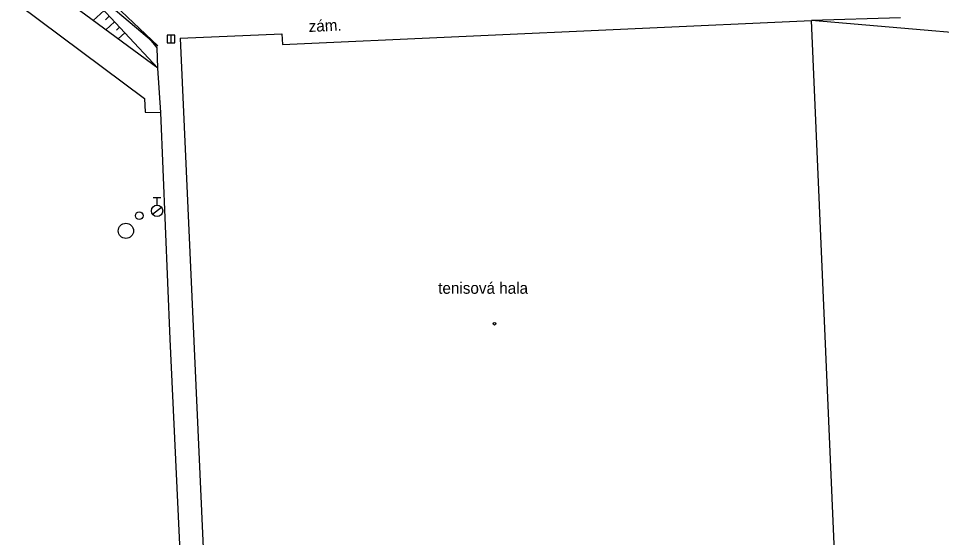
# Model space of a CAD drawing. Extents: x -737812 to -729375, y -1123000 to -1115500.
# Drawn here: x -736312.1 to -736251.3, y -1118316.3 to -1118282.1 of the extents above; entities that cross this region are included whole.
import ezdxf

# ---------------------------------------------------------------- set-up
doc = ezdxf.new("R2010")
doc.units = 0
for name, color, linetype in [('Doplněk polohopisu', 7, 'Continuous'), ('Pomocné popisy', 7, 'Continuous'), ('Popisy budov', 7, 'Continuous'), ('Povr_ zn_ inž_ sítí - kan_', 7, 'Continuous'), ('Povr_ zn_ inž_ sítí - vod_', 7, 'Continuous'), ('Stavební objekty', 7, 'Continuous'), ('Výškopis', 7, 'Continuous'), ('Značky druhů budov', 7, 'Continuous')]:
    doc.layers.add(name, color=color, linetype=linetype)

msp = doc.modelspace()

# ---------------------------------------------------------------- linework, layer by layer
at = {"layer": 'Doplněk polohopisu'}
for p, q in [((-736302.92, -1118285.4), (-736310.03, -1118280.13)), ((-736254.05, -1118282.07), (-736259.89, -1118282.26)), ((-736302.95, -1118284.06), (-736303.41, -1118283.49)), ((-736302.92, -1118285.4), (-736302.95, -1118284.06)), ((-736302.71, -1118288.3), (-736302.92, -1118285.4)), ((-736302.09, -1118303.23), (-736302.71, -1118288.3)), ((-736300.95, -1118328.07), (-736302.09, -1118303.23))]:
    msp.add_line(p, q, dxfattribs=at)
msp.add_lwpolyline([(-736312.08, -1118281.2), (-736303.78, -1118287.39), (-736303.74, -1118288.28), (-736302.71, -1118288.3)], dxfattribs=at)
at = {"layer": 'Povr_ zn_ inž_ sítí - kan_'}
msp.add_line((-736302.05, -1118283.22), (-736302.05, -1118283.72), dxfattribs=at)
msp.add_lwpolyline([(-736302.301, -1118283.22), (-736302.301, -1118283.721), (-736301.799, -1118283.72), (-736301.8, -1118283.22)], close=True, dxfattribs=at)
msp.add_circle((-736305.01, -1118296.1), 0.5, dxfattribs=at)
at = {"layer": 'Povr_ zn_ inž_ sítí - vod_'}
for p, q in [((-736303.21, -1118293.905), (-736302.71, -1118293.905)), ((-736302.96, -1118294.405), (-736302.96, -1118293.905)), ((-736303.254, -1118295.011), (-736302.664, -1118294.548))]:
    msp.add_line(p, q, dxfattribs=at)
for centre, radius in [((-736302.96, -1118294.78), 0.375), ((-736304.13, -1118295.1), 0.25)]:
    msp.add_circle(centre, radius, dxfattribs=at)
at = {"layer": 'Stavební objekty'}
for points in [[(-736301.43, -1118283.42), (-736299.64, -1118323.3), (-736292.95, -1118323), (-736292.93, -1118322.31), (-736258.23, -1118320.78), (-736259.89, -1118282.26)], [(-736294.74, -1118283.13), (-736294.71, -1118283.83), (-736259.89, -1118282.26)], [(-736301.43, -1118283.42), (-736294.74, -1118283.13)]]:
    msp.add_lwpolyline(points, dxfattribs=at)
at = {"layer": 'Výškopis'}
for p, q in [((-736302.92, -1118285.4), (-736308.16, -1118279.76)), ((-736307.27, -1118280.22), (-736302.92, -1118283.93)), ((-736306.45, -1118281.6), (-736307.16, -1118282.26)), ((-736305.71, -1118281.26), (-736302.92, -1118283.93)), ((-736306.11, -1118281.97), (-736306.36, -1118282.21)), ((-736305.77, -1118282.34), (-736306.34, -1118282.87)), ((-736305.43, -1118282.7), (-736305.63, -1118282.89)), ((-736305.09, -1118283.07), (-736305.52, -1118283.47))]:
    msp.add_line(p, q, dxfattribs=at)
msp.add_lwpolyline([(-736236.89, -1118285.37), (-736242.01, -1118286.9), (-736243.02, -1118283.7), (-736259.89, -1118282.26)], dxfattribs=at)
at = {"layer": 'Značky druhů budov'}
msp.add_circle((-736280.75, -1118302.21), 0.0875, dxfattribs=at)

# ---------------------------------------------------------------- texts
at = {"layer": 'Pomocné popisy'}
msp.add_text('zám.', height=0.75, rotation=2.51313, dxfattribs=at).set_placement((-736292.97, -1118283.01))
at = {"layer": 'Popisy budov'}
msp.add_text('tenisová hala', height=0.75, dxfattribs=at).set_placement((-736284.46, -1118300.24))

doc.saveas('drawing.dxf')
